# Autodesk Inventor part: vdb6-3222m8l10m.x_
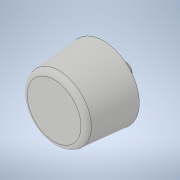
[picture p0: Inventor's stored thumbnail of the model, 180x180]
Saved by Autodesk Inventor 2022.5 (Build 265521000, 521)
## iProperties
Created: 2021-08
Part Number: vdb6-3222m8l10m.x_
Material: 一般
Document SubType Name: Modeling
Designer: ImaoCorp
Density: 1 g/cm^3
Appearance: 既定
Sending System: SOLIDWORKS 2019-2019304
MC: AMD64
MC_MODEL: Intel64 Family 6 Model 60 Stepping 3, GenuineIntel
OS: Windows_NT
FRU: Parasolid Version 31.0, build 290,  9- 1-2019
FORMAT: text
GUISE: transmit
KEY: vdb6-3222m8l10m
FILE: vdb6-3222m8l10m.x_t
DATE: Wed Aug 11 15:00:49 2021
Author: ImaoCorp
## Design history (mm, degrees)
feature "Base1"
node "ソリッド1"
